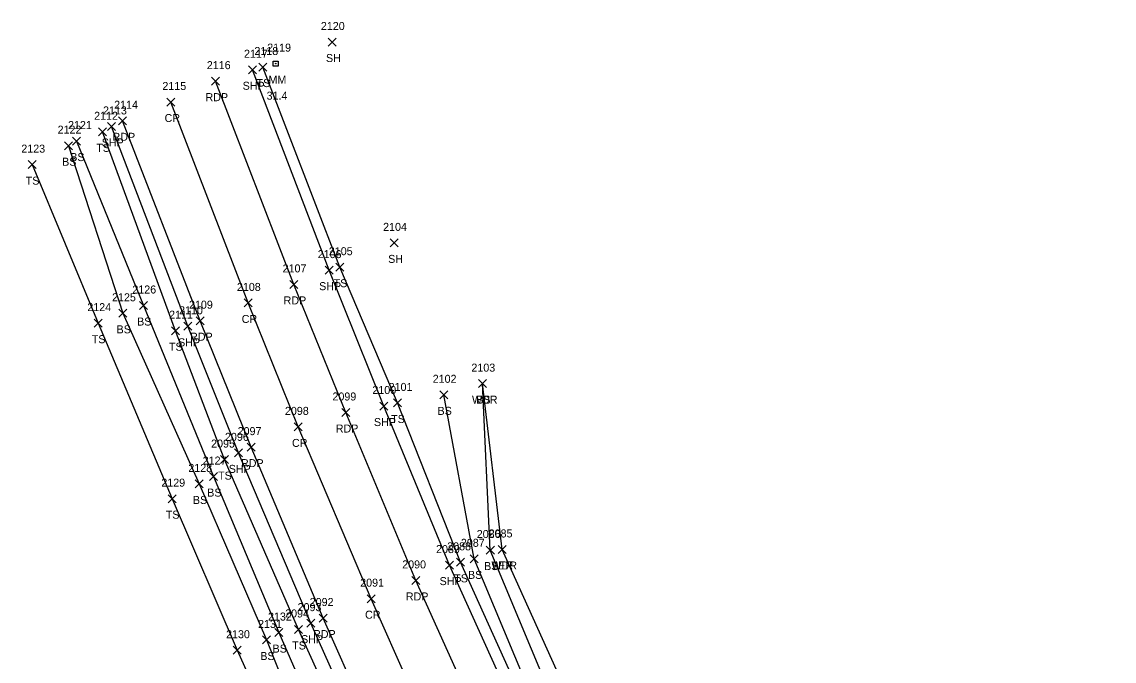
# Model space of a CAD drawing. Extents: x 1647574 to 1652703, y 212895 to 228670.
# Drawn here: x 1647843.3 to 1648116.3, y 228510.8 to 228670.4 of the extents above; entities that cross this region are included whole.
import ezdxf

# ---------------------------------------------------------------- set-up
doc = ezdxf.new("R2010")
doc.units = 0
for name, color, linetype in [('L_A', 7, 'Continuous'), ('L_I', 7, 'Continuous'), ('L_TIC', 7, 'Continuous'), ('LARO', 7, 'Continuous'), ('LAWA', 7, 'Continuous'), ('LELB', 7, 'Continuous'), ('P_A', 7, 'Continuous'), ('P_I', 7, 'Continuous'), ('P_TIC', 7, 'Continuous'), ('PET', 7, 'Continuous'), ('PRC', 7, 'Continuous'), ('PSP', 7, 'Continuous'), ('S_A', 7, 'Continuous'), ('S_C', 7, 'Continuous'), ('S_I', 7, 'Continuous'), ('SRM', 7, 'Continuous')]:
    doc.layers.add(name, color=color, linetype=linetype)

msp = doc.modelspace()

# ---------------------------------------------------------------- linework, layer by layer
at = {"layer": 'L_TIC'}
for points in [[(1647919.82, 228664.35), (1647921.82, 228666.35)], [(1647921.82, 228664.35), (1647919.82, 228666.35)], [(1647902.55, 228658.1), (1647904.55, 228660.1)], [(1647904.55, 228658.1), (1647902.55, 228660.1)], [(1647855.99, 228639.62), (1647857.99, 228641.62)], [(1647857.99, 228639.62), (1647855.99, 228641.62)], [(1647862.51, 228641.93), (1647864.51, 228643.93)], [(1647864.51, 228641.93), (1647862.51, 228643.93)], [(1647853.94, 228638.46), (1647855.94, 228640.46)], [(1647855.94, 228638.46), (1647853.94, 228640.46)], [(1647844.88, 228633.73), (1647846.88, 228635.73)], [(1647846.88, 228633.73), (1647844.88, 228635.73)], [(1647935.36, 228614.2), (1647937.36, 228616.2)], [(1647937.36, 228614.2), (1647935.36, 228616.2)], [(1647921.81, 228608.12), (1647923.81, 228610.12)], [(1647923.81, 228608.12), (1647921.81, 228610.12)], [(1647867.55, 228596.62), (1647869.55, 228598.62)], [(1647869.55, 228596.62), (1647867.55, 228598.62)], [(1647872.68, 228598.56), (1647874.68, 228600.56)], [(1647874.68, 228598.56), (1647872.68, 228600.56)], [(1647861.38, 228594.15), (1647863.38, 228596.15)], [(1647863.38, 228594.15), (1647861.38, 228596.15)], [(1647880.68, 228592.27), (1647882.68, 228594.27)], [(1647882.68, 228592.27), (1647880.68, 228594.27)], [(1647957.42, 228579.05), (1647959.42, 228581.05)], [(1647959.42, 228579.05), (1647957.42, 228581.05)], [(1647957.42, 228579.05), (1647959.42, 228581.05)], [(1647959.42, 228579.05), (1647957.42, 228581.05)], [(1647936.18, 228574.23), (1647938.18, 228576.23)], [(1647938.18, 228574.23), (1647936.18, 228576.23)], [(1647947.75, 228576.26), (1647949.75, 228578.26)], [(1647949.75, 228576.26), (1647947.75, 228578.26)], [(1647892.94, 228560.09), (1647894.94, 228562.09)], [(1647894.94, 228560.09), (1647892.94, 228562.09)], [(1647890.2, 228555.85), (1647892.2, 228557.85)], [(1647892.2, 228555.85), (1647890.2, 228557.85)], [(1647886.62, 228554.01), (1647888.62, 228556.01)], [(1647888.62, 228554.01), (1647886.62, 228556.01)], [(1647879.87, 228550.33), (1647881.87, 228552.33)], [(1647881.87, 228550.33), (1647879.87, 228552.33)], [(1647959.38, 228537.51), (1647961.38, 228539.51)], [(1647961.38, 228537.51), (1647959.38, 228539.51)], [(1647962.3, 228537.65), (1647964.3, 228539.65)], [(1647964.3, 228537.65), (1647962.3, 228539.65)], [(1647962.3, 228537.65), (1647964.3, 228539.65)], [(1647964.3, 228537.65), (1647962.3, 228539.65)], [(1647951.94, 228534.44), (1647953.94, 228536.44)], [(1647953.94, 228534.44), (1647951.94, 228536.44)], [(1647955.36, 228535.31), (1647957.36, 228537.31)], [(1647957.36, 228535.31), (1647955.36, 228537.31)], [(1647906.52, 228516.9), (1647908.52, 228518.9)], [(1647908.52, 228516.9), (1647906.52, 228518.9)], [(1647911.45, 228517.68), (1647913.45, 228519.68)], [(1647913.45, 228517.68), (1647911.45, 228519.68)], [(1647903.47, 228515.05), (1647905.47, 228517.05)], [(1647905.47, 228515.05), (1647903.47, 228517.05)], [(1647896.13, 228512.49), (1647898.13, 228514.49)], [(1647898.13, 228512.49), (1647896.13, 228514.49)]]:
    msp.add_lwpolyline(points, dxfattribs=at)
at = {"layer": 'LARO'}
msp.add_lwpolyline([(1648079.64, 228304.78), (1648056.82, 228344.46), (1648035.58, 228381.97), (1648016.5, 228417.39), (1648009.32, 228443.2), (1647999.94, 228459.06), (1647981.12, 228499.17), (1647963.3, 228538.65)], dxfattribs=at)
at = {"layer": 'LAWA'}
msp.add_lwpolyline([(1647963.3, 228538.65), (1647958.42, 228580.05)], dxfattribs=at)
at = {"layer": 'LELB'}
for points in [[(1648354.19, 227879.71), (1648321.73, 227919.78), (1648297.18, 227952.21), (1648269.36, 227989.06), (1648243.48, 228024.19), (1648219.28, 228058.75), (1648195.05, 228094.29), (1648173.04, 228128.05), (1648150.23, 228163.27), (1648127.62, 228199.76), (1648103.9, 228239.37), (1648088.91, 228265.67), (1648069.89, 228299.68), (1648049.11, 228338.12), (1648027.69, 228377.44), (1648010.08, 228413.76), (1647990.03, 228455.24), (1647972, 228493.31), (1647952.94, 228535.44), (1647937.18, 228575.23), (1647922.81, 228609.12), (1647903.55, 228659.1)], [(1648351.84, 227812.3), (1648319.03, 227851.85), (1648287.09, 227892.13), (1648260.82, 227925.49), (1648232.83, 227963.62), (1648207.81, 227997.28), (1648182.57, 228032.91), (1648159.55, 228068.16), (1648135.13, 228103.7), (1648112.63, 228139.57), (1648088.44, 228176.61), (1648065.81, 228216.55), (1648048.77, 228244.34), (1648030.34, 228278.62), (1648010.32, 228316.28), (1647988.24, 228358.51), (1647969.05, 228396.12), (1647949.58, 228436.76), (1647932.55, 228474.27), (1647912.45, 228518.68), (1647893.94, 228561.09), (1647881.68, 228593.27), (1647863.51, 228642.93)], [(1647854.94, 228639.46), (1647868.55, 228597.62), (1647887.62, 228555.01), (1647904.47, 228516.05), (1647919.16, 228479.08), (1647930.46, 228457.29), (1647929.66, 228443.74)], [(1647856.99, 228640.62), (1647873.68, 228599.56), (1647891.2, 228556.85), (1647907.52, 228517.9), (1647923.71, 228480.87), (1647932.61, 228458), (1647947.17, 228430.71), (1647957.46, 228407.87), (1647973.05, 228375.23), (1647990.12, 228338.71), (1648007.66, 228306.18), (1648026.86, 228269.73), (1648050.03, 228227.83), (1648068.63, 228195.13), (1648090.12, 228158.96), (1648103.63, 228129.11), (1648111.3, 228097.1)], [(1647845.88, 228634.73), (1647862.38, 228595.15), (1647880.87, 228551.33), (1647897.13, 228513.49), (1647913.95, 228476.13), (1647925.23, 228454.3), (1647929.66, 228443.74)], [(1648187.85, 228134.14), (1648161.26, 228169.32), (1648135.31, 228208.01), (1648112.05, 228244.65), (1648095.88, 228270.18), (1648077.48, 228303.1), (1648054.77, 228342.44), (1648033.29, 228380.08), (1648013.94, 228416.05), (1647995, 228457.05), (1647977.86, 228496.65), (1647960.38, 228538.51), (1647958.42, 228580.05)], [(1648199.35, 228096.72), (1648181.76, 228131.34), (1648157.62, 228167.73), (1648133.38, 228206.23), (1648109.51, 228242.64), (1648092.98, 228267.74), (1648072.08, 228300.5), (1648051.47, 228339.28), (1648029.72, 228378.51), (1648011.8, 228414.44), (1647991.85, 228456.05), (1647973.95, 228494.28), (1647956.36, 228536.31), (1647948.75, 228577.26)]]:
    msp.add_lwpolyline(points, dxfattribs=at)
at = {"layer": 'P_TIC'}
for points in [[(1647899.95, 228657.43), (1647901.95, 228659.43)], [(1647901.95, 228657.43), (1647899.95, 228659.43)], [(1647890.72, 228654.58), (1647892.72, 228656.58)], [(1647892.72, 228654.58), (1647890.72, 228656.58)], [(1647879.56, 228649.37), (1647881.56, 228651.37)], [(1647881.56, 228649.37), (1647879.56, 228651.37)], [(1647864.74, 228643.27), (1647866.74, 228645.27)], [(1647866.74, 228643.27), (1647864.74, 228645.27)], [(1647867.51, 228644.68), (1647869.51, 228646.68)], [(1647869.51, 228644.68), (1647867.51, 228646.68)], [(1647919.08, 228607.39), (1647921.08, 228609.39)], [(1647921.08, 228607.39), (1647919.08, 228609.39)], [(1647910.25, 228603.83), (1647912.25, 228605.83)], [(1647912.25, 228603.83), (1647910.25, 228605.83)], [(1647898.83, 228599.2), (1647900.83, 228601.2)], [(1647900.83, 228599.2), (1647898.83, 228601.2)], [(1647883.83, 228593.37), (1647885.83, 228595.37)], [(1647885.83, 228593.37), (1647883.83, 228595.37)], [(1647886.86, 228594.77), (1647888.86, 228596.77)], [(1647888.86, 228594.77), (1647886.86, 228596.77)], [(1647923.27, 228571.85), (1647925.27, 228573.85)], [(1647925.27, 228571.85), (1647923.27, 228573.85)], [(1647932.77, 228573.46), (1647934.77, 228575.46)], [(1647934.77, 228573.46), (1647932.77, 228575.46)], [(1647911.39, 228568.25), (1647913.39, 228570.25)], [(1647913.39, 228568.25), (1647911.39, 228570.25)], [(1647899.58, 228563.2), (1647901.58, 228565.2)], [(1647901.58, 228563.2), (1647899.58, 228565.2)], [(1647896.47, 228561.77), (1647898.47, 228563.77)], [(1647898.47, 228561.77), (1647896.47, 228563.77)], [(1647949.16, 228533.75), (1647951.16, 228535.75)], [(1647951.16, 228533.75), (1647949.16, 228535.75)], [(1647940.78, 228529.92), (1647942.78, 228531.92)], [(1647942.78, 228529.92), (1647940.78, 228531.92)], [(1647929.63, 228525.36), (1647931.63, 228527.36)], [(1647931.63, 228525.36), (1647929.63, 228527.36)], [(1647917.59, 228520.53), (1647919.59, 228522.53)], [(1647919.59, 228520.53), (1647917.59, 228522.53)], [(1647914.56, 228519.25), (1647916.56, 228521.25)], [(1647916.56, 228519.25), (1647914.56, 228521.25)]]:
    msp.add_lwpolyline(points, dxfattribs=at)
at = {"layer": 'PET'}
for points in [[(1648343.92, 227872.68), (1648312.18, 227912.42), (1648286.41, 227945.97), (1648259.83, 227981.4), (1648233.53, 228017.77), (1648209.68, 228051.59), (1648184.99, 228088.05), (1648163.33, 228121.58), (1648140.14, 228157.28), (1648117.89, 228193.29), (1648093.86, 228233.11), (1648077.72, 228260.65), (1648058.67, 228294.21), (1648038.3, 228331.93), (1648017.64, 228371.82), (1647998.92, 228408.85), (1647978.83, 228450.17), (1647961.14, 228487.91), (1647941.78, 228530.92), (1647924.27, 228572.85), (1647911.25, 228604.83), (1647891.72, 228655.58)], [(1648357.18, 227817.31), (1648324.35, 227856.66), (1648291.64, 227897.48), (1648266.75, 227930.03), (1648238.87, 227967.44), (1648213.55, 228002.24), (1648188.8, 228037.85), (1648165.1, 228072.75), (1648141.89, 228108.1), (1648118.76, 228143.77), (1648095.78, 228180.92), (1648072, 228220.25), (1648055.45, 228249.03), (1648036.53, 228282.02), (1648016.46, 228319.63), (1647994.47, 228361.74), (1647975.95, 228398.72), (1647955.9, 228439.51), (1647938.47, 228476.92), (1647918.59, 228521.53), (1647900.58, 228564.2), (1647887.86, 228595.77), (1647868.51, 228645.68)]]:
    msp.add_lwpolyline(points, dxfattribs=at)
at = {"layer": 'PRC'}
msp.add_lwpolyline([(1648367.06, 227824.4), (1648333.96, 227865.19), (1648301.98, 227905.03), (1648276.56, 227937.83), (1648249.38, 227974.31), (1648223.31, 228010.17), (1648199.56, 228044.67), (1648175.52, 228080.05), (1648153.19, 228113.7), (1648129.37, 228150.61), (1648107.24, 228186.18), (1648083.17, 228226.08), (1648067.05, 228254.73), (1648048.14, 228287.63), (1648028.02, 228325.77), (1648005.9, 228366.87), (1647988.06, 228403.42), (1647967.46, 228445.07), (1647950.09, 228482.37), (1647930.63, 228526.36), (1647912.39, 228569.25), (1647899.83, 228600.2), (1647880.56, 228650.37)], dxfattribs=at)
at = {"layer": 'PSP'}
for points in [[(1648352.03, 227878.52), (1648319.68, 227918.25), (1648294.86, 227950.71), (1648267.61, 227987.28), (1648241.44, 228023.36), (1648217.73, 228057.32), (1648192.95, 228093.18), (1648170.97, 228126.69), (1648148.28, 228162.02), (1648125.62, 228198.28), (1648101.68, 228238.38), (1648086.46, 228264.28), (1648067.22, 228298.38), (1648046.56, 228336.73), (1648025.86, 228376.38), (1648007.42, 228412.68), (1647987.18, 228453.92), (1647969.46, 228492.06), (1647950.16, 228534.75), (1647933.77, 228574.46), (1647920.08, 228608.39), (1647900.95, 228658.43)], [(1648354.02, 227814.19), (1648321.06, 227853.92), (1648288.58, 227894.46), (1648263.39, 227927.38), (1648235.52, 227964.75), (1648210.1, 227999.58), (1648185.31, 228035.32), (1648161.26, 228070.47), (1648138.25, 228105.61), (1648115.28, 228141.45), (1648092.15, 228178.84), (1648068.52, 228217.79), (1648052.14, 228246.38), (1648033.46, 228279.87), (1648013.32, 228317.27), (1647991.27, 228359.8), (1647972.51, 228396.99), (1647952.45, 228438.14), (1647935.54, 228475.52), (1647915.56, 228520.25), (1647897.47, 228562.77), (1647884.83, 228594.37), (1647865.74, 228644.27)]]:
    msp.add_lwpolyline(points, dxfattribs=at)
at = {"layer": 'SRM'}
msp.add_lwpolyline([(1647906.14, 228660.57), (1647907.39, 228660.57), (1647907.39, 228659.32), (1647906.14, 228659.32)], close=True, dxfattribs=at)
msp.add_circle((1647906.76, 228659.95), 0.0833, dxfattribs=at)

# ---------------------------------------------------------------- texts
at = {"layer": 'L_A'}
for s, p in [('SH', (1647919.31, 228660.35)), ('TS', (1647901.96, 228654.1)), ('TS', (1647861.92, 228637.93)), ('BS', (1647853.38, 228634.46)), ('BS', (1647855.43, 228635.62)), ('TS', (1647844.29, 228629.73)), ('SH', (1647934.85, 228610.2)), ('TS', (1647921.22, 228604.12)), ('BS', (1647872.12, 228594.56)), ('BS', (1647866.99, 228592.62)), ('TS', (1647860.79, 228590.15)), ('TS', (1647880.09, 228588.27)), ('WDR', (1647955.79, 228575.05)), ('BS', (1647956.86, 228575.05)), ('BS', (1647947.19, 228572.26)), ('TS', (1647935.59, 228570.23)), ('TS', (1647892.35, 228556.09)), ('BS', (1647886.06, 228550.01)), ('BS', (1647889.64, 228551.85)), ('TS', (1647879.28, 228546.33)), ('BS', (1647958.82, 228533.51)), ('WDR', (1647960.66, 228533.65)), ('LER', (1647960.88, 228533.65)), ('TS', (1647951.35, 228530.44)), ('BS', (1647954.8, 228531.31)), ('BS', (1647905.96, 228512.9)), ('TS', (1647910.86, 228513.68)), ('BS', (1647902.91, 228511.05))]:
    msp.add_text(s, height=2, dxfattribs=at).set_placement(p)
at = {"layer": 'L_I'}
for s, p in [('2120', (1647918.04, 228668.35)), ('2118', (1647901.43, 228662.1)), ('2112', (1647861.38, 228645.93)), ('2122', (1647852.25, 228642.46)), ('2121', (1647854.86, 228643.62)), ('2123', (1647843.19, 228637.73)), ('2104', (1647933.59, 228618.2)), ('2105', (1647920.03, 228612.12)), ('2126', (1647870.93, 228602.56)), ('2125', (1647865.86, 228600.62)), ('2124', (1647859.68, 228598.15)), ('2111', (1647880.12, 228596.27)), ('2103', (1647955.65, 228583.05)), ('2103', (1647955.65, 228583.05)), ('2102', (1647945.98, 228580.26)), ('2101', (1647934.97, 228578.23)), ('2095', (1647890.61, 228564.09)), ('2128', (1647884.92, 228558.01)), ('2127', (1647888.51, 228559.85)), ('2129', (1647878.17, 228554.33)), ('2086', (1647956.99, 228541.51)), ('2085', (1647959.96, 228541.65)), ('2085', (1647959.96, 228541.65)), ('2087', (1647953.02, 228539.31)), ('2088', (1647949.6, 228538.44)), ('2132', (1647904.83, 228520.9)), ('2094', (1647909.11, 228521.68)), ('2131', (1647902.34, 228519.05)), ('2130', (1647894.35, 228516.49))]:
    msp.add_text(s, height=2, dxfattribs=at).set_placement(p)
at = {"layer": 'P_A'}
for s, p in [('SHP', (1647898.49, 228653.43)), ('RDP', (1647889.21, 228650.58)), ('CR', (1647878.99, 228645.37)), ('RDP', (1647865.99, 228640.68)), ('SHP', (1647863.28, 228639.27)), ('SHP', (1647917.61, 228603.39)), ('RDP', (1647908.73, 228599.83)), ('CR', (1647898.26, 228595.2)), ('RDP', (1647885.35, 228590.77)), ('SHP', (1647882.36, 228589.37)), ('SHP', (1647931.3, 228569.46)), ('RDP', (1647921.76, 228567.85)), ('CR', (1647910.83, 228564.25)), ('SHP', (1647895.01, 228557.77)), ('RDP', (1647898.07, 228559.2)), ('SHP', (1647947.7, 228529.75)), ('RDP', (1647939.27, 228525.92)), ('CR', (1647929.07, 228521.36)), ('SHP', (1647913.09, 228515.25)), ('RDP', (1647916.08, 228516.53))]:
    msp.add_text(s, height=2, dxfattribs=at).set_placement(p)
at = {"layer": 'P_I'}
for s, p in [('2117', (1647898.83, 228661.43)), ('2116', (1647889.54, 228658.58)), ('2115', (1647878.44, 228653.37)), ('2114', (1647866.38, 228648.68)), ('2113', (1647863.61, 228647.27)), ('2106', (1647917.25, 228611.39)), ('2107', (1647908.48, 228607.83)), ('2108', (1647897.06, 228603.2)), ('2109', (1647885.09, 228598.77)), ('2110', (1647882.61, 228597.37)), ('2100', (1647930.91, 228577.46)), ('2099', (1647920.93, 228575.85)), ('2098', (1647909.06, 228572.25)), ('2097', (1647897.24, 228567.2)), ('2096', (1647894.08, 228565.77)), ('2089', (1647946.82, 228537.75)), ('2090', (1647938.36, 228533.92)), ('2091', (1647927.86, 228529.36)), ('2093', (1647912.22, 228523.25)), ('2092', (1647915.25, 228524.53))]:
    msp.add_text(s, height=2, dxfattribs=at).set_placement(p)
at = {"layer": 'S_A'}
msp.add_text('MM', height=2, dxfattribs=at).set_placement((1647904.95, 228654.95))
at = {"layer": 'S_C'}
msp.add_text('31.4', height=2, dxfattribs=at).set_placement((1647904.48, 228650.95))
at = {"layer": 'S_I'}
msp.add_text('2119', height=2, dxfattribs=at).set_placement((1647904.63, 228662.95))

doc.saveas('drawing.dxf')
